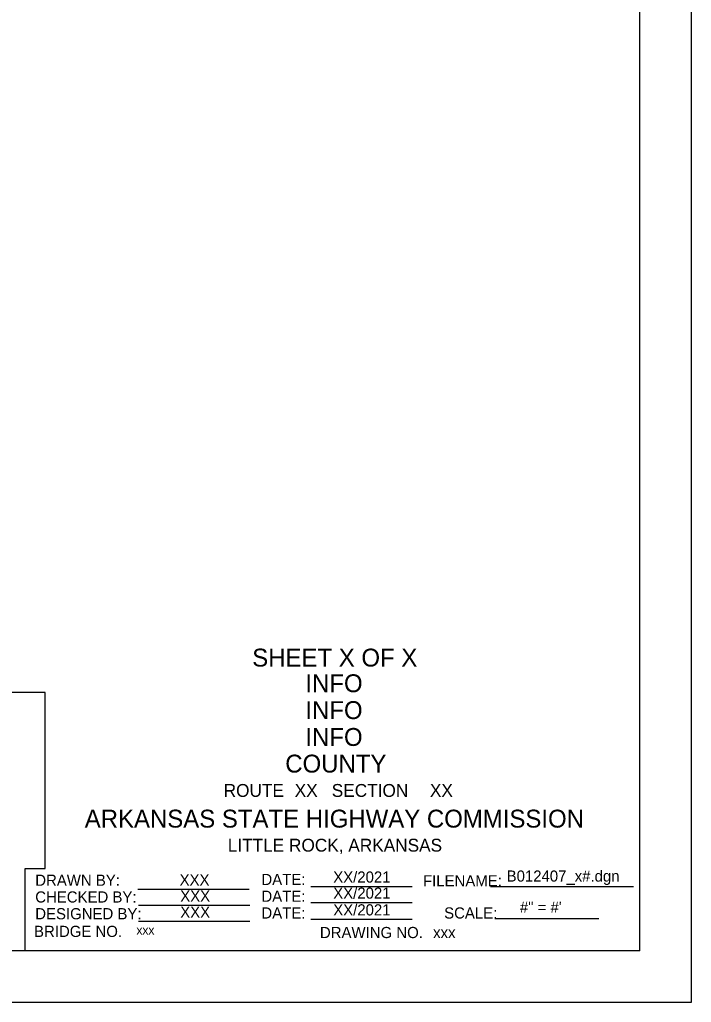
# Model space of a CAD drawing. Extents: x 16 to 1228740, y 11 to 152440.
# Drawn here: x 17.864 to 18.49, y 10.709 to 11.626 of the extents above; entities that cross this region are included whole.
import ezdxf

# ---------------------------------------------------------------- set-up
doc = ezdxf.new("R2010")
doc.units = 0
for name, color, linetype in [('B_Copy In', 7, 'Continuous'), ('B_Text', 7, 'Continuous'), ('B_Title Text', 7, 'Continuous'), ('R_Border', 7, 'Continuous'), ('R_No Plot', 7, 'Continuous')]:
    doc.layers.add(name, color=color, linetype=linetype)

msp = doc.modelspace()

# ---------------------------------------------------------------- linework, layer by layer
at = {"layer": 'B_Text'}
for p, q in [((18.13559, 10.81765), (18.23009, 10.81765)), ((18.30318, 10.81765), (18.43623, 10.81765)), ((17.97449, 10.81515), (18.07809, 10.81515)), ((17.97509, 10.80015), (18.07869, 10.80015)), ((18.13559, 10.80265), (18.23009, 10.80265)), ((18.13559, 10.80265), (18.23009, 10.80265)), ((17.97509, 10.78515), (18.07869, 10.78515)), ((18.13559, 10.78703), (18.23009, 10.78703)), ((18.30706, 10.78765), (18.40419, 10.78765))]:
    msp.add_line(p, q, dxfattribs=at)
at = {"layer": 'R_Border'}
for q in [(18.44221, 12.49475), (15.78327, 10.75755)]:
    msp.add_line((18.44221, 10.75755), q, dxfattribs=at)
msp.add_lwpolyline([(15.65694, 12.54282), (18.49027, 12.54282), (18.49027, 10.70949), (15.65694, 10.70949)], close=True, dxfattribs=at)
at = {"layer": 'R_No Plot'}
for p, q in [((17.888, 10.99864), (17.47349, 10.99864)), ((17.888, 10.83424), (17.888, 10.99864)), ((17.86946, 10.83424), (17.888, 10.83424)), ((17.86946, 10.75755), (17.86946, 10.83424))]:
    msp.add_line(p, q, dxfattribs=at)

# ---------------------------------------------------------------- texts
at = {"layer": 'B_Copy In'}
for s, height, p in [('SHEET X OF X', 0.0167, (18.08103, 11.02272)), ('INFO', 0.0167, (18.13057, 10.99878)), ('INFO', 0.0167, (18.13057, 10.97373)), ('INFO', 0.0167, (18.13057, 10.94868)), ('COUNTY', 0.0167, (18.11181, 10.92383)), ('XX', 0.012, (18.12061, 10.90115)), ('XX', 0.012, (18.24664, 10.90115)), ('XXX', 0.0104, (18.01335, 10.81846)), ('XX/2021', 0.0104, (18.15654, 10.82119)), ('B012407_x#.dgn', 0.0104, (18.31817, 10.8221)), ('XX/2021', 0.0104, (18.15654, 10.80619)), ('XXX', 0.0104, (18.01395, 10.80346)), ('XXX', 0.0104, (18.01395, 10.78846)), ('XX/2021', 0.0104, (18.15654, 10.79057)), ('#" = #\'', 0.0104, (18.3305, 10.79302)), ('xxx', 0.008333, (17.97312, 10.77269)), ('xxx', 0.010417, (18.24962, 10.76944))]:
    msp.add_text(s, height=height, dxfattribs=at).set_placement(p)
at = {"layer": 'B_Text'}
for s, height, p in [('DRAWN BY:', 0.010417, (17.87879, 10.8182)), ('DATE:', 0.010417, (18.08959, 10.8189)), ('FILENAME:', 0.010417, (18.24018, 10.81765)), ('CHECKED BY:', 0.0104166, (17.87879, 10.80257)), ('DATE:', 0.010417, (18.08959, 10.80328)), ('DESIGNED BY:', 0.0104166, (17.87879, 10.78695)), ('DATE:', 0.010417, (18.08959, 10.78765)), ('SCALE:', 0.010417, (18.25989, 10.78765)), ('BRIDGE NO.', 0.010417, (17.87767, 10.77048)), ('DRAWING NO.', 0.0104166, (18.14412, 10.76942))]:
    msp.add_text(s, height=height, dxfattribs=at).set_placement(p)
at = {"layer": 'B_Title Text'}
for s, height, p in [('ROUTE          SECTION ', 0.012, (18.0544, 10.90115)), ('ARKANSAS STATE HIGHWAY COMMISSION', 0.0167, (17.92492, 10.8725)), ('LITTLE ROCK, ARKANSAS', 0.012, (18.05823, 10.85007))]:
    msp.add_text(s, height=height, dxfattribs=at).set_placement(p)

doc.saveas('drawing.dxf')
